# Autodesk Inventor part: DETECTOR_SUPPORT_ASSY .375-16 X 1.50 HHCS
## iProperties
Shininess: 64.0
Length Units: 11272
Angle Units: 11279
Time Units: 11290
Mass Units: 11286
Length Display Precision: 3
Angle Display Precision: 2
Compacted: True
Part Number: DETECTOR_SUPPORT_ASSY .375-16 X 1.50 HHCS
Document SubType Name: Modeling
Created: 2004-08
Designer: John Blackburn
Material: STAINLESS_STEEL, AUSTENITIC
Manufacturer: Standard
Standards Organization: Custom
Density: 0.0
Volumn: 0.0
Area: 0.0
PropertySet Name: Model Information
Control State: 0
Master: False
Checked Out: False
Author: John Blackburn
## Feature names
1. Base1
